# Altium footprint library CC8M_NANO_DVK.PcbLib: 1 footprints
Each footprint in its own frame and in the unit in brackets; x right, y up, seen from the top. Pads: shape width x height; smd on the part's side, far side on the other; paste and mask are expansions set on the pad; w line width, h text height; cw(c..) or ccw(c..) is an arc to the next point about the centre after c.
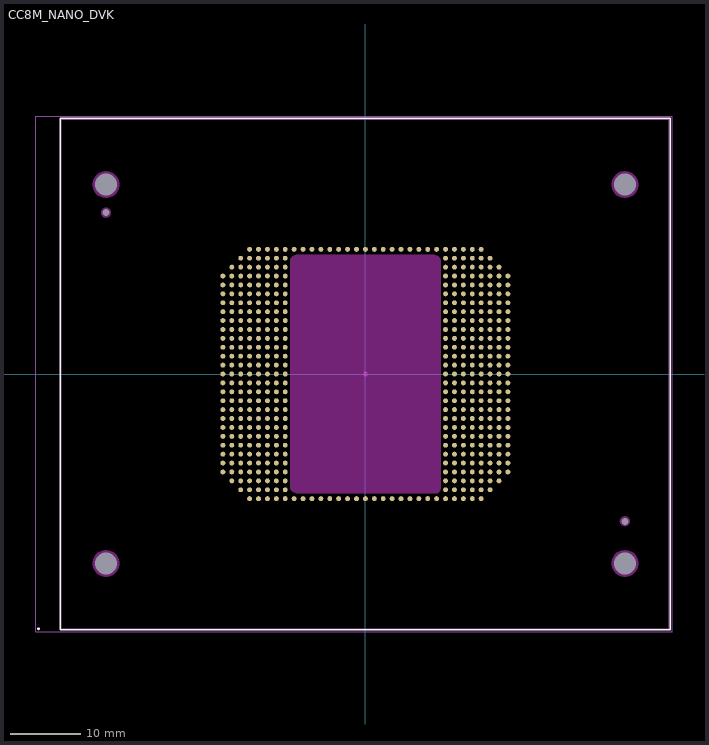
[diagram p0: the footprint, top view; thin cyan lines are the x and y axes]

## CC8M_NANO_DVK [mm]
height 5
pads (480):
  round 0.7 smd: A4(-20.32,-13.97) A5(-20.32,-12.7) A6(-20.32,-11.43) A7(-20.32,-10.16) A8(-20.32,-8.89) A9(-20.32,-7.62) A10(-20.32,-6.35) A11(-20.32,-5.08) A12(-20.32,-3.81) A13(-20.32,-2.54) A14(-20.32,-1.27) A15(-20.32,0) A16(-20.32,1.27) A17(-20.32,2.54) A18(-20.32,3.81) A19(-20.32,5.08) A20(-20.32,6.35) A21(-20.32,7.62) A22(-20.32,8.89) A23(-20.32,10.16) A24(-20.32,11.43) A25(-20.32,12.7) A26(-20.32,13.97) AA1(5.08,-17.78) AA29(5.08,17.78) AB1(6.35,-17.78) AB29(6.35,17.78) AC1(7.62,-17.78) AC29(7.62,17.78) AD1(8.89,-17.78) AD29(8.89,17.78) AE1(10.16,-17.78) AE29(10.16,17.78) AF1(11.43,-17.78) AF2(11.43,-16.51) AF3(11.43,-15.24) AF4(11.43,-13.97) AF5(11.43,-12.7) AF6(11.43,-11.43) AF7(11.43,-10.16) AF8(11.43,-8.89) AF9(11.43,-7.62) AF10(11.43,-6.35) AF11(11.43,-5.08) AF12(11.43,-3.81) AF13(11.43,-2.54) AF14(11.43,-1.27) AF15(11.43,0) AF16(11.43,1.27) AF17(11.43,2.54) AF18(11.43,3.81) AF19(11.43,5.08) AF20(11.43,6.35) AF21(11.43,7.62) AF22(11.43,8.89) AF23(11.43,10.16) AF24(11.43,11.43) AF25(11.43,12.7) AF26(11.43,13.97) AF27(11.43,15.24) AF28(11.43,16.51) AF29(11.43,17.78) AG1(12.7,-17.78) AG2(12.7,-16.51) AG3(12.7,-15.24) AG4(12.7,-13.97) AG5(12.7,-12.7) AG6(12.7,-11.43) AG7(12.7,-10.16) AG8(12.7,-8.89) AG9(12.7,-7.62) AG10(12.7,-6.35) AG11(12.7,-5.08) AG12(12.7,-3.81) AG13(12.7,-2.54) AG14(12.7,-1.27) AG15(12.7,0) AG16(12.7,1.27) AG17(12.7,2.54) AG18(12.7,3.81) AG19(12.7,5.08) AG20(12.7,6.35) AG21(12.7,7.62) AG22(12.7,8.89) AG23(12.7,10.16) AG24(12.7,11.43) AG25(12.7,12.7) AG26(12.7,13.97) AG27(12.7,15.24) AG28(12.7,16.51) AG29(12.7,17.78) AH1(13.97,-17.78) AH2(13.97,-16.51) AH3(13.97,-15.24) AH4(13.97,-13.97) AH5(13.97,-12.7) AH6(13.97,-11.43) AH7(13.97,-10.16) AH8(13.97,-8.89) AH9(13.97,-7.62) AH10(13.97,-6.35) AH11(13.97,-5.08) AH12(13.97,-3.81) AH13(13.97,-2.54) AH14(13.97,-1.27) AH15(13.97,0) AH16(13.97,1.27) AH17(13.97,2.54) AH18(13.97,3.81) AH19(13.97,5.08) AH20(13.97,6.35) AH21(13.97,7.62) AH22(13.97,8.89) AH23(13.97,10.16) AH24(13.97,11.43) AH25(13.97,12.7) AH26(13.97,13.97) AH27(13.97,15.24) AH28(13.97,16.51) AH29(13.97,17.78) AJ1(15.24,-17.78) AJ2(15.24,-16.51) AJ3(15.24,-15.24) AJ4(15.24,-13.97) AJ5(15.24,-12.7) AJ6(15.24,-11.43) AJ7(15.24,-10.16) AJ8(15.24,-8.89) AJ9(15.24,-7.62) AJ10(15.24,-6.35) AJ11(15.24,-5.08) AJ12(15.24,-3.81) AJ13(15.24,-2.54) AJ14(15.24,-1.27) AJ15(15.24,0) AJ16(15.24,1.27) AJ17(15.24,2.54) AJ18(15.24,3.81) AJ19(15.24,5.08) AJ20(15.24,6.35) AJ21(15.24,7.62) AJ22(15.24,8.89) AJ23(15.24,10.16) AJ24(15.24,11.43) AJ25(15.24,12.7) AJ26(15.24,13.97) AJ27(15.24,15.24) AJ28(15.24,16.51) AJ29(15.24,17.78) AK1(16.51,-17.78) AK2(16.51,-16.51) AK3(16.51,-15.24) AK4(16.51,-13.97) AK5(16.51,-12.7) AK6(16.51,-11.43) AK7(16.51,-10.16) AK8(16.51,-8.89) AK9(16.51,-7.62) AK10(16.51,-6.35) AK11(16.51,-5.08) AK12(16.51,-3.81) AK13(16.51,-2.54) AK14(16.51,-1.27) AK15(16.51,0) AK16(16.51,1.27) AK17(16.51,2.54) AK18(16.51,3.81) AK19(16.51,5.08) AK20(16.51,6.35) AK21(16.51,7.62) AK22(16.51,8.89) AK23(16.51,10.16) AK24(16.51,11.43) AK25(16.51,12.7) AK26(16.51,13.97) AK27(16.51,15.24) AK28(16.51,16.51) AK29(16.51,17.78) AL2(17.78,-16.51) AL3(17.78,-15.24) AL4(17.78,-13.97) AL5(17.78,-12.7) AL6(17.78,-11.43) AL7(17.78,-10.16) AL8(17.78,-8.89) AL9(17.78,-7.62) AL10(17.78,-6.35) AL11(17.78,-5.08) AL12(17.78,-3.81) AL13(17.78,-2.54) AL14(17.78,-1.27) AL15(17.78,0) AL16(17.78,1.27) AL17(17.78,2.54) AL18(17.78,3.81) AL19(17.78,5.08) AL20(17.78,6.35) AL21(17.78,7.62) AL22(17.78,8.89) AL23(17.78,10.16) AL24(17.78,11.43) AL25(17.78,12.7) AL26(17.78,13.97) AL27(17.78,15.24) AL28(17.78,16.51) AM3(19.05,-15.24) AM4(19.05,-13.97) AM5(19.05,-12.7) AM6(19.05,-11.43) AM7(19.05,-10.16) AM8(19.05,-8.89) AM9(19.05,-7.62) AM10(19.05,-6.35) AM11(19.05,-5.08) AM12(19.05,-3.81) AM13(19.05,-2.54) AM14(19.05,-1.27) AM15(19.05,0) AM16(19.05,1.27) AM17(19.05,2.54) AM18(19.05,3.81) AM19(19.05,5.08) AM20(19.05,6.35) AM21(19.05,7.62) AM22(19.05,8.89) AM23(19.05,10.16) AM24(19.05,11.43) AM25(19.05,12.7) AM26(19.05,13.97) AM27(19.05,15.24) AN4(20.32,-13.97) AN5(20.32,-12.7) AN6(20.32,-11.43) AN7(20.32,-10.16) AN8(20.32,-8.89) AN9(20.32,-7.62) AN10(20.32,-6.35) AN11(20.32,-5.08) AN12(20.32,-3.81) AN13(20.32,-2.54) AN14(20.32,-1.27) AN15(20.32,0) AN16(20.32,1.27) AN17(20.32,2.54) AN18(20.32,3.81) AN19(20.32,5.08) AN20(20.32,6.35) AN21(20.32,7.62) AN22(20.32,8.89) AN23(20.32,10.16) AN24(20.32,11.43) AN25(20.32,12.7) AN26(20.32,13.97) B3(-19.05,-15.24) B4(-19.05,-13.97) B5(-19.05,-12.7) B6(-19.05,-11.43) B7(-19.05,-10.16) B8(-19.05,-8.89) B9(-19.05,-7.62) B10(-19.05,-6.35) B11(-19.05,-5.08) B12(-19.05,-3.81) B13(-19.05,-2.54) B14(-19.05,-1.27) B15(-19.05,0) B16(-19.05,1.27) B17(-19.05,2.54) B18(-19.05,3.81) B19(-19.05,5.08) B20(-19.05,6.35) B21(-19.05,7.62) B22(-19.05,8.89) B23(-19.05,10.16) B24(-19.05,11.43) B25(-19.05,12.7) B26(-19.05,13.97) B27(-19.05,15.24) C2(-17.78,-16.51) C3(-17.78,-15.24) C4(-17.78,-13.97) C5(-17.78,-12.7) C6(-17.78,-11.43) C7(-17.78,-10.16) C8(-17.78,-8.89) C9(-17.78,-7.62) C10(-17.78,-6.35) C11(-17.78,-5.08) C12(-17.78,-3.81) C13(-17.78,-2.54) C14(-17.78,-1.27) C15(-17.78,0) C16(-17.78,1.27) C17(-17.78,2.54) C18(-17.78,3.81) C19(-17.78,5.08) C20(-17.78,6.35) C21(-17.78,7.62) C22(-17.78,8.89) C23(-17.78,10.16) C24(-17.78,11.43) C25(-17.78,12.7) C26(-17.78,13.97) C27(-17.78,15.24) C28(-17.78,16.51) D1(-16.51,-17.78) D2(-16.51,-16.51) D3(-16.51,-15.24) D4(-16.51,-13.97) D5(-16.51,-12.7) D6(-16.51,-11.43) D7(-16.51,-10.16) D8(-16.51,-8.89) D9(-16.51,-7.62) D10(-16.51,-6.35) D11(-16.51,-5.08) D12(-16.51,-3.81) D13(-16.51,-2.54) D14(-16.51,-1.27) D15(-16.51,0) D16(-16.51,1.27) D17(-16.51,2.54) D18(-16.51,3.81) D19(-16.51,5.08) D20(-16.51,6.35) D21(-16.51,7.62) D22(-16.51,8.89) D23(-16.51,10.16) D24(-16.51,11.43) D25(-16.51,12.7) D26(-16.51,13.97) D27(-16.51,15.24) D28(-16.51,16.51) D29(-16.51,17.78) E1(-15.24,-17.78) E2(-15.24,-16.51) E3(-15.24,-15.24) E4(-15.24,-13.97) E5(-15.24,-12.7) E6(-15.24,-11.43) E7(-15.24,-10.16) E8(-15.24,-8.89) E9(-15.24,-7.62) E10(-15.24,-6.35) E11(-15.24,-5.08) E12(-15.24,-3.81) E13(-15.24,-2.54) E14(-15.24,-1.27) E15(-15.24,0) E16(-15.24,1.27) E17(-15.24,2.54) E18(-15.24,3.81) E19(-15.24,5.08) E20(-15.24,6.35) E21(-15.24,7.62) E22(-15.24,8.89) E23(-15.24,10.16) E24(-15.24,11.43) E25(-15.24,12.7) E26(-15.24,13.97) E27(-15.24,15.24) E28(-15.24,16.51) E29(-15.24,17.78) F1(-13.97,-17.78) F2(-13.97,-16.51) F3(-13.97,-15.24) F4(-13.97,-13.97) F5(-13.97,-12.7) F6(-13.97,-11.43) F7(-13.97,-10.16) F8(-13.97,-8.89) F9(-13.97,-7.62) F10(-13.97,-6.35) F11(-13.97,-5.08) F12(-13.97,-3.81) F13(-13.97,-2.54) F14(-13.97,-1.27) F15(-13.97,0) F16(-13.97,1.27) F17(-13.97,2.54) F18(-13.97,3.81) F19(-13.97,5.08) F20(-13.97,6.35) F21(-13.97,7.62) F22(-13.97,8.89) F23(-13.97,10.16) F24(-13.97,11.43) F25(-13.97,12.7) F26(-13.97,13.97) F27(-13.97,15.24) F28(-13.97,16.51) F29(-13.97,17.78) G1(-12.7,-17.78) G2(-12.7,-16.51) G3(-12.7,-15.24) G4(-12.7,-13.97) G5(-12.7,-12.7) G6(-12.7,-11.43) G7(-12.7,-10.16) G8(-12.7,-8.89) G9(-12.7,-7.62) G10(-12.7,-6.35) G11(-12.7,-5.08) G12(-12.7,-3.81) G13(-12.7,-2.54) G14(-12.7,-1.27) G15(-12.7,0) G16(-12.7,1.27) G17(-12.7,2.54) G18(-12.7,3.81) G19(-12.7,5.08) G20(-12.7,6.35) G21(-12.7,7.62) G22(-12.7,8.89) G23(-12.7,10.16) G24(-12.7,11.43) G25(-12.7,12.7) G26(-12.7,13.97) G27(-12.7,15.24) G28(-12.7,16.51) G29(-12.7,17.78) H1(-11.43,-17.78) H2(-11.43,-16.51) H3(-11.43,-15.24) H4(-11.43,-13.97) H5(-11.43,-12.7) H6(-11.43,-11.43) H7(-11.43,-10.16) H8(-11.43,-8.89) H9(-11.43,-7.62) H10(-11.43,-6.35) H11(-11.43,-5.08) H12(-11.43,-3.81) H13(-11.43,-2.54) H14(-11.43,-1.27) H15(-11.43,0) H16(-11.43,1.27) H17(-11.43,2.54) H18(-11.43,3.81) H19(-11.43,5.08) H20(-11.43,6.35) H21(-11.43,7.62) H22(-11.43,8.89) H23(-11.43,10.16) H24(-11.43,11.43) H25(-11.43,12.7) H26(-11.43,13.97) H27(-11.43,15.24) H28(-11.43,16.51) H29(-11.43,17.78) J1(-10.16,-17.78) J29(-10.16,17.78) K1(-8.89,-17.78) K29(-8.89,17.78) L1(-7.62,-17.78) L29(-7.62,17.78) M1(-6.35,-17.78) M29(-6.35,17.78) N1(-5.08,-17.78) N29(-5.08,17.78) P1(-3.81,-17.78) P29(-3.81,17.78) R1(-2.54,-17.78) R29(-2.54,17.78) T1(-1.27,-17.78) T29(-1.27,17.78) U1(0,-17.78) U29(0,17.78) V1(1.27,-17.78) V29(1.27,17.78) W1(2.54,-17.78) W29(2.54,17.78) Y1(3.81,-17.78) Y29(3.81,17.78)
  round 0 hole 3.15: MH1(-37,27) MH2(37,27) MH3(37,-27) MH4(-37,-27)
  round 0 hole 1: MH5(-37,23) MH6(37,-21)
Top Overlay:
  circle w0.2: c-46.625,-36.337 r0.1
  lines w0.2: -43.5,-36.5 43.5,-36.5 43.5,36.5 -43.5,36.5 -43.5,-36.5
Keep-Out Layer:
  board cut-out: -10.75,16 -10.75,-16 -10.75,-16.098 -10.712,-16.292 -10.636,-16.474 -10.527,-16.638 -10.388,-16.777 -10.224,-16.886 -10.042,-16.962 -9.848,-17 -9.75,-17 10,-17 10.074,-17 10.219,-16.971 10.355,-16.915 10.478,-16.833 10.583,-16.728 10.665,-16.605 10.721,-16.469 10.75,-16.324 10.75,-16.25 10.75,16 10.75,16.098 10.712,16.292 10.636,16.474 10.527,16.637 10.387,16.777 10.224,16.886 10.042,16.962 9.848,17 9.75,17 -9.75,17 -9.848,17 -10.042,16.962 -10.224,16.886 -10.387,16.777 -10.527,16.637 -10.636,16.474 -10.712,16.292 -10.75,16.099
Keep-Out Layer:
  drawing of 6 lines, arcs and shapes, not listed
Mechanical 3:
  lines w0.1: -43.375,-36.35 43.35,-36.35 43.35,36.35 -43.375,36.35
  lines w0.102: -43.375,-36.35 -43.348,2.5 ; -43.375,2.325 -43.375,36.35 ; -43.375,27 -43.375,32.25
  text ".Designator" at -41.75,34.25 h1
Drill Drawing:
  lines w0.102: -10.758,14.258 -8.003,17.003 ; -10.75,6.675 -0.392,16.992 ; -10.75,10.425 -4.171,16.996 ; -10.745,-9.93 -2.358,-1.572 ; -10.745,-5.63 -4.863,0.233 ; -10.745,-0.93 7.236,16.989 ; -10.745,2.87 3.442,17.008 ; -10.743,-14.082 1.777,-1.607 ; -9.773,-17.002 5.677,-1.607 ; -5.801,-16.999 10.741,-0.516 ; -3.85,1.62 10.753,16.172 ; 0.45,1.62 10.746,11.879 ; 0.855,-17.005 10.747,-7.147 ; 4.183,-17.008 10.75,-10.463 ; 4.95,1.62 10.75,7.4 ; 6.15,-1.08 10.748,3.502 ; 7.51,-17.01 10.741,-13.791 ; 9.976,-4.597 -2.473,-17.002 10.738,-3.838 ; -10.75,-16.414 -10.164,-17 10.29,-17 10.75,-16.54 10.75,16.414 10.164,17 -10.164,17 -10.75,16.414 -10.75,-16.414 ; -4.85,-1.58 -4.85,1.62 6.15,1.62 6.15,-1.58 -4.85,-1.58
  text "Cut Out" at -4.05,-0.78 h1.52
Mechanical 20:
  circle w0.05: c0,0 r0.25
  lines w0.05: -0.35,0 0.35,0 ; 0,-0.35 0,0.35 ; -47,-36.75 -47,36.75 43.75,36.75 43.75,-36.75 -47,-36.75
3D body "ConnectCore 8M Nano SoM - 3D STEP blue2.STEP": height 3.77, standoff -0.6, extent -22.5,-20 22.5,20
